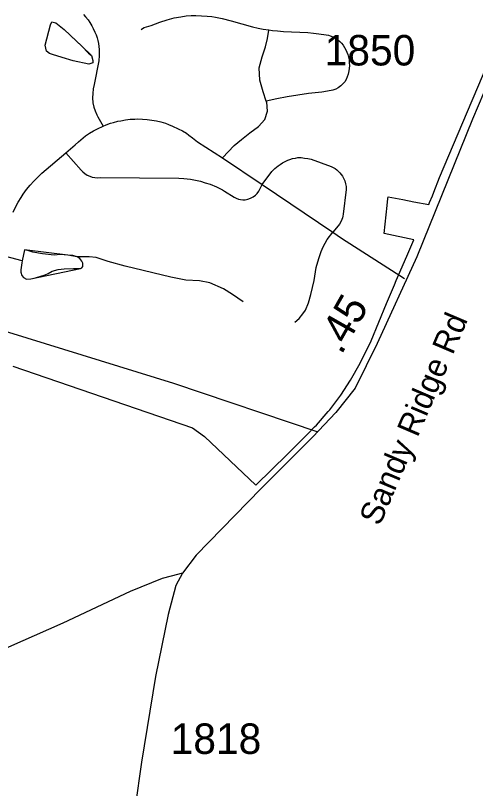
# Model space of a CAD drawing. Extents: x 1662474 to 1856135, y 779280 to 917889.
# Drawn here: x 1700283 to 1702171, y 841271 to 844441 of the extents above; entities that cross this region are included whole.
import ezdxf

# ---------------------------------------------------------------- set-up
doc = ezdxf.new("R2010")
doc.units = 0
for name, color, linetype in [('Exist Boundary Political City Limit New', 7, 'Continuous'), ('Exist Hydrographic Misc Water Feature', 7, 'Continuous'), ('Exist Road Non-System Type 51', 7, 'Continuous'), ('Exist Road Secondary Mileage Tenths English Label', 7, 'Continuous'), ('Exist Road Secondary Type 51 Attributed', 7, 'Continuous'), ('Exist Road Secondary Type 51 Label', 7, 'Continuous'), ('Exist Road Secondary Type 51 Number Label', 7, 'Continuous'), ('Map Preparation Boundary City Limit Buffer Line', 7, 'Continuous')]:
    doc.layers.add(name, color=color, linetype=linetype)

msp = doc.modelspace()

# ---------------------------------------------------------------- linework, layer by layer
at = {"layer": 'Exist Boundary Political City Limit New'}
msp.add_lwpolyline([(1700271.9, 843003.2), (1701008.9, 842750.2), (1701058.6, 842714.9), (1701269.2, 842514.6), (1701399.5, 842642.3), (1701464, 842706.9), (1701470.4, 842713.3), (1701481.6, 842724.7), (1701510.6, 842753.8), (1701518.5, 842761.6), (1701566.4, 842816.6), (1701572.9, 842823.9), (1701617.9, 842884.7), (1701657.5, 842945.9), (1701697.1, 843014.8), (1701742.2, 843107.4), (1701805.4, 843260.2), (1701838, 843336.4), (1701845.5, 843353.9), (1701879.1, 843432.1), (1701892.8, 843463.9), (1701917.1, 843521), (1701795.6, 843547.4), (1701808.5, 843662.4), (1701811.6, 843690.6), (1701812.4, 843697.3), (1701872.4, 843686.2), (1701917.8, 843677.5), (1701978.8, 843665.8), (1701982.4, 843674.4), (1701993.8, 843701.6), (1701999.9, 843716.4), (1702023.6, 843777.2), (1702294.6, 844417.6)], dxfattribs=at)
at = {"layer": 'Exist Hydrographic Misc Water Feature'}
for points in [[(1700474.9, 844268.7), (1700434.9, 844281), (1700423.1, 844285.4), (1700411.1, 844295.4), (1700405.5, 844319.4), (1700426.5, 844403.5), (1700432.6, 844414.8), (1700448.6, 844411.2), (1700482.4, 844384.3), (1700533.6, 844335.6), (1700555.4, 844315.5), (1700582.8, 844287.1), (1700594.7, 844277), (1700600.6, 844257.1), (1700600.5, 844246.5), (1700584.5, 844241.1), (1700520.5, 844255.5), (1700474.9, 844268.7)], [(1700474.9, 844268.7), (1700434.9, 844281), (1700423.1, 844285.4), (1700411.1, 844295.4), (1700405.5, 844319.4), (1700426.5, 844403.5), (1700432.6, 844414.8), (1700448.6, 844411.2), (1700482.4, 844384.3), (1700555.4, 844315.5), (1700594.7, 844277), (1700600.6, 844257.1), (1700600.5, 844246.5), (1700584.5, 844241.1), (1700520.5, 844255.5), (1700474.9, 844268.7)], [(1700311.1, 843435.1), (1700216.1, 843460), (1700178.3, 843472.2), (1700114.6, 843505.5), (1700051.1, 843536.3), (1700001.1, 843548.8), (1699949.2, 843555.6), (1699841.5, 843568.5), (1699777.6, 843575.6), (1699728.1, 843578.2)], [(1700535.8, 843451.8), (1700518.4, 843456.3), (1700498, 843458.3), (1700466, 843460.6), (1700441.9, 843458.6), (1700394.6, 843463.7), (1700354.1, 843470.3), (1700338.2, 843476.3), (1700320.3, 843480.8), (1700311.1, 843435.1)], [(1700535.8, 843451.8), (1700498, 843458.3), (1700320.3, 843480.8), (1700311.1, 843435.1)], [(1700311.1, 843435.1), (1700309.6, 843426.9), (1700305.1, 843398.2), (1700305.5, 843388.4), (1700308.9, 843374.4), (1700316.5, 843366), (1700328.5, 843360), (1700345.6, 843361.3), (1700364.8, 843365.8), (1700404.8, 843377.3), (1700417.4, 843383.6), (1700433.3, 843393.2), (1700458.1, 843400.1), (1700483.2, 843402), (1700521.2, 843403.7), (1700549.3, 843403.2), (1700555.8, 843406.3), (1700559.4, 843411.2), (1700559, 843425.1), (1700555.6, 843433.3), (1700546.7, 843444.2), (1700535.8, 843451.8)], [(1700311.1, 843435.1), (1700309.6, 843426.9), (1700305.1, 843398.2), (1700305.5, 843388.4), (1700308.9, 843374.4), (1700316.5, 843366), (1700328.5, 843360), (1700345.6, 843361.3), (1700549.3, 843403.2), (1700555.8, 843406.3), (1700559.4, 843411.2), (1700559, 843425.1), (1700555.6, 843433.3), (1700546.7, 843444.2), (1700535.8, 843451.8)], [(1701217.4, 843266.4), (1701173.9, 843296.9), (1701136.3, 843319.8), (1701080.5, 843344.7), (1701038.6, 843353), (1700982.6, 843355.7), (1700921, 843368.5), (1700733.4, 843413.3), (1700663.6, 843432), (1700613.9, 843448.6), (1700585.7, 843450.8), (1700535.8, 843451.8)]]:
    msp.add_lwpolyline(points, dxfattribs=at)
at = {"layer": 'Exist Road Non-System Type 51'}
msp.add_line((1701295.2, 843747.7), (1701585.8, 843551.9), dxfattribs=at)
for points in [[(1700562.1, 844444.8), (1700570.6, 844435.6), (1700580.9, 844423), (1700587.9, 844413), (1700596.6, 844399.1), (1700602.4, 844388.1), (1700609.1, 844373.4), (1700613.6, 844361.9), (1700617.9, 844350.2), (1700620.6, 844338.5), (1700623.4, 844326.4), (1700625.4, 844313.9), (1700626.5, 844302), (1700627, 844289.4), (1700627.2, 844277.6), (1700625.6, 844255.5), (1700606, 844157.7), (1700602.1, 844140.6), (1700599.9, 844121.7), (1700599.4, 844102.8), (1700601.2, 844083.6), (1700605.1, 844065), (1700609.9, 844049.5), (1700616.5, 844034), (1700620.9, 844024.9), (1700642.5, 843987.2)], [(1700798.9, 844383.2), (1700803.9, 844387.6), (1700810.8, 844391.4), (1700839.8, 844400.6), (1700875.4, 844413.8), (1700906.1, 844423.8), (1700934.6, 844431.1), (1700961.4, 844436.2), (1700983.8, 844439.1), (1701004.1, 844440.6), (1701023.4, 844441), (1701046.6, 844440.2), (1701069.5, 844438.9), (1701088.6, 844436.8), (1701104.5, 844434.1), (1701130.9, 844428.4), (1701168.1, 844419.4), (1701255.5, 844394.8), (1701278.6, 844389.3), (1701299.6, 844385.4), (1701322.6, 844381.9)], [(1701312.5, 844089.8), (1701299.6, 844128.1), (1701285.4, 844176.1), (1701283.1, 844225.9), (1701295.2, 844271.2), (1701309.2, 844313.2), (1701317.6, 844347.4), (1701322.6, 844381.2), (1701322.6, 844381.9)], [(1701322.6, 844381.9), (1701337.6, 844379.9), (1701358.8, 844377.6), (1701382.4, 844375.8), (1701483.1, 844371.1), (1701506.4, 844369), (1701527.5, 844366.2), (1701558.5, 844362.4), (1701567.1, 844360.5), (1701574.6, 844358.2), (1701585.5, 844353.6), (1701595.9, 844347.9), (1701605.4, 844341.6), (1701613.8, 844334.7), (1701620.9, 844327.4), (1701627.6, 844319.1), (1701633.8, 844310), (1701639.1, 844300.4), (1701643.4, 844291), (1701646.9, 844280.9), (1701649.8, 844270), (1701651.8, 844258.8), (1701653, 844247.2), (1701653.4, 844235.6), (1701652.8, 844224.4), (1701651.2, 844213.9), (1701648.4, 844200.8), (1701644.5, 844188.9), (1701639.9, 844178.5), (1701634.5, 844169.7), (1701627, 844160.7), (1701618, 844152.3), (1701607.9, 844145), (1701597.2, 844139.2), (1701585, 844134.9), (1701563.4, 844130.2), (1701540.1, 844126.6), (1701485.4, 844121.2), (1701442, 844114.9), (1701398.6, 844107.4), (1701355.5, 844099.1), (1701312.5, 844089.8)], [(1701132, 843856.9), (1701180.1, 843907.6), (1701210, 843932.9), (1701244.9, 843960.2), (1701279.8, 843986.5), (1701305.9, 844014.2), (1701317.8, 844049.2), (1701313.9, 844085.8), (1701312.5, 844089.8)], [(1700642.5, 843987.2), (1700654.9, 843992.5), (1700672.9, 843998.9), (1700685, 844002.5), (1700703.6, 844007.2), (1700716, 844009.6), (1700734.9, 844013.2), (1700753.8, 844015.7), (1700772.9, 844016.4), (1700785.5, 844016.7), (1700804.6, 844016.2), (1700823.9, 844014.4), (1700842.8, 844012), (1700861.4, 844009.1), (1700880, 844004.4), (1700898.4, 843998.9), (1700910.4, 843994.7), (1700927.8, 843987.6), (1700951.1, 843976.9), (1700967.9, 843967.9), (1700984.5, 843957.9), (1700995, 843950.9), (1701010.1, 843939.2), (1701029.6, 843923.2), (1701132, 843856.9), (1701295.2, 843747.7)], [(1700489.8, 843877.4), (1700527.8, 843910.2), (1700541.4, 843923), (1700551.1, 843931.4), (1700571.1, 843947.2), (1700586.9, 843957.9), (1700603.1, 843967.9), (1700619.9, 843976.9), (1700642.5, 843987.2)], [(1700274.2, 843634.2), (1700283.9, 843655.2), (1700294.8, 843675.5), (1700306.5, 843695.4), (1700314.9, 843708.4), (1700328.1, 843726.9), (1700342.8, 843744.8), (1700358, 843762.1), (1700374.2, 843778.4), (1700391.4, 843793.9), (1700489.8, 843877.4)], [(1700489.8, 843877.4), (1700553, 843806.2), (1700559.5, 843799.9), (1700568.1, 843792.9), (1700577.9, 843786.8), (1700587.9, 843782.1), (1700598.4, 843778.7), (1700609.4, 843776.2), (1700620.6, 843776), (1700630.1, 843776.2), (1700953, 843773.7), (1700974, 843772.6), (1701001.2, 843769.4), (1701021.8, 843765.5), (1701042.5, 843761.4), (1701062.1, 843755.2), (1701081.9, 843748.8), (1701107.4, 843738.2), (1701132.2, 843725.6), (1701141.4, 843720.4), (1701180.5, 843695.9), (1701188.9, 843691.5), (1701197.9, 843688.4), (1701206.8, 843686.2), (1701216.2, 843685.5), (1701225.4, 843685.8), (1701236.9, 843687.9), (1701248, 843691.5), (1701258.5, 843697), (1701267.6, 843703.9), (1701275, 843711.4), (1701281.1, 843720.1), (1701284.8, 843725.9), (1701295.2, 843747.7)], [(1701295.2, 843747.7), (1701334.9, 843800.7), (1701347.4, 843813.5), (1701361.1, 843825.1), (1701368.6, 843830.6), (1701378.6, 843836.7), (1701389.6, 843842.4), (1701400.5, 843847.4), (1701408.6, 843850), (1701420.1, 843854), (1701432, 843856.4), (1701441.1, 843858.2), (1701455.4, 843858.2), (1701469.2, 843856.4), (1701483.1, 843854.5), (1701497.1, 843851.4), (1701579.1, 843821.9), (1701587.1, 843817.8), (1701594.6, 843813), (1701601.5, 843808), (1701608.1, 843802), (1701614.4, 843795.7), (1701619.9, 843789.2), (1701624.9, 843781.8), (1701629.1, 843773.9), (1701634.1, 843762.9), (1701637.5, 843751.4), (1701639.6, 843739.8), (1701640.4, 843727.8), (1701627.8, 843626.7), (1701626.4, 843618.2), (1701624.4, 843610.7), (1701619.4, 843597.9), (1701612.5, 843585.5), (1701607.2, 843578.7), (1701585.8, 843551.9)], [(1701429.6, 843183.7), (1701446.9, 843198.4), (1701462.4, 843217), (1701473.9, 843233.2), (1701485.2, 843262.9), (1701494.6, 843297), (1701508.1, 843355), (1701517, 843408), (1701528.2, 843444.8), (1701537.1, 843472.9), (1701546.1, 843492.9), (1701562.4, 843521.9), (1701585.8, 843551.9)], [(1701585.8, 843551.9), (1701621.4, 843528.2), (1701880, 843362.9)], [(1701525.6, 842732.5), (1700933.2, 842932.4), (1700255.4, 843141.4), (1700242.5, 843146.6), (1700233.4, 843151.1), (1700221, 843157.9), (1700203.9, 843169.8), (1700187.9, 843182.6), (1700180.5, 843189.9), (1700171.1, 843200.2), (1700162.6, 843211.2), (1700153, 843225.4), (1700130.9, 843266.9), (1700122.2, 843281.9), (1700112.4, 843296.5), (1700093.4, 843323), (1700065.4, 843356.4)]]:
    msp.add_lwpolyline(points, dxfattribs=at)
at = {"layer": 'Exist Road Secondary Type 51 Attributed'}
for points in [[(1702204.4, 844125.7), (1702157.9, 844015.5), (1701930.3, 843451), (1701767.2, 843096.1), (1701677.4, 842912.2), (1701598, 842813), (1701502.7, 842713.8), (1701290.3, 842500.5), (1701024.6, 842228.3), (1700968.9, 842154.1)], [(1700968.9, 842154.1), (1700922.5, 842142), (1700884.5, 842131.8), (1700753.5, 842078.4), (1700477.5, 841948.5), (1700194.3, 841824.1), (1699997.6, 841739.5), (1699890.8, 841683.8), (1699789.2, 841631.9), (1699671.7, 841559.4), (1699214.1, 841216.3), (1699154, 841172.8), (1699106.3, 841139.6), (1699020, 841090.1), (1698968.2, 841069.4), (1698920.5, 841054.9), (1698815.5, 841035.4), (1698647.4, 841017), (1698478.9, 841005.5), (1698249.6, 840985.5), (1698098.8, 840966.6), (1697991.4, 840957.4)], [(1700968.9, 842154.1), (1700941.1, 842103.9), (1700909.5, 841984.2), (1700857.6, 841730.1), (1700799.9, 841379.1), (1700773.7, 841195.7), (1700768.4, 840959.9), (1700778.9, 840760.8), (1700805.1, 840462.1), (1700841.8, 840263), (1700860.2, 840107.7), (1700864.6, 840035.7), (1700874.3, 839910.9), (1700870.6, 839772.1)]]:
    msp.add_lwpolyline(points, dxfattribs=at)
at = {"layer": 'Map Preparation Boundary City Limit Buffer Line'}
msp.add_lwpolyline([(1700271.9, 843003.2), (1701008.9, 842750.2), (1701058.6, 842714.9), (1701269.2, 842514.6), (1701399.5, 842642.3), (1701464, 842706.9), (1701470.4, 842713.3), (1701481.6, 842724.7), (1701510.6, 842753.8), (1701518.5, 842761.6), (1701566.4, 842816.6), (1701572.9, 842823.9), (1701617.9, 842884.7), (1701657.5, 842945.9), (1701697.1, 843014.8), (1701742.2, 843107.4), (1701805.4, 843260.2), (1701838, 843336.4), (1701845.5, 843353.9), (1701879.1, 843432.1), (1701892.8, 843463.9), (1701917.1, 843521), (1701795.6, 843547.4), (1701808.5, 843662.4), (1701811.6, 843690.6), (1701812.4, 843697.3), (1701872.4, 843686.2), (1701917.8, 843677.5), (1701978.8, 843665.8), (1701982.4, 843674.4), (1701993.8, 843701.6), (1701999.9, 843716.4), (1702023.6, 843777.2), (1702294.6, 844417.6)], dxfattribs=at)

# ---------------------------------------------------------------- texts
at = {"layer": 'Exist Road Secondary Mileage Tenths English Label'}
msp.add_text('.45', height=125, rotation=60.4474, dxfattribs=at).set_placement((1701620.5, 843046.5))
at = {"layer": 'Exist Road Secondary Type 51 Label'}
msp.add_text('Sandy Ridge Rd', height=95, rotation=66.8935, dxfattribs=at).set_placement((1701777.8, 842344.1))
at = {"layer": 'Exist Road Secondary Type 51 Number Label'}
for s, p in [('1850', (1701551.9, 844236.2)), ('1818', (1700920, 841412.9))]:
    msp.add_text(s, height=125, dxfattribs=at).set_placement(p)

doc.saveas('drawing.dxf')
